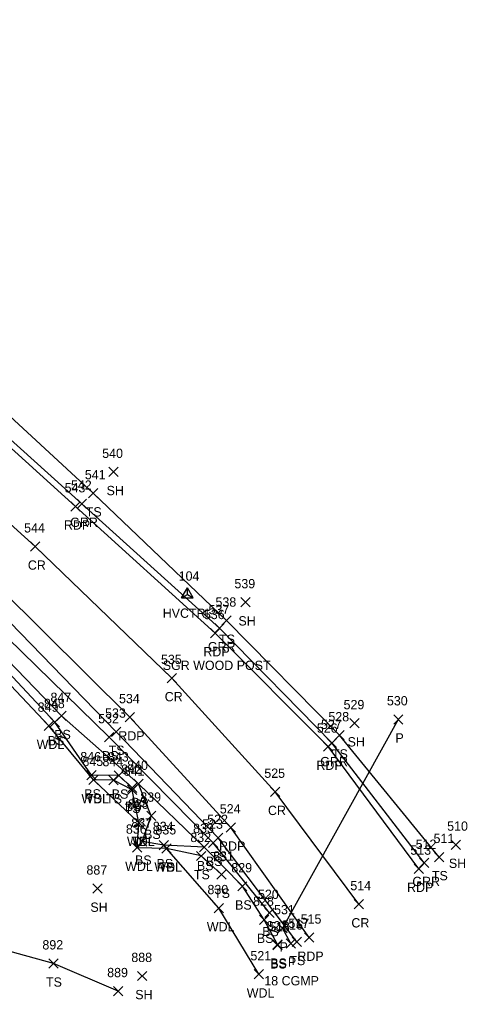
# Model space of a CAD drawing. Extents: x 1879695 to 1880991, y 836466 to 845172.
# Drawn here: x 1880183.9 to 1880280.2, y 844011.6 to 844222.2 of the extents above; entities that cross this region are included whole.
import ezdxf

# ---------------------------------------------------------------- set-up
doc = ezdxf.new("R2010")
doc.units = 0
for name, color, linetype in [('C_A', 7, 'Continuous'), ('C_I', 7, 'Continuous'), ('CPSM', 7, 'Continuous'), ('D_A', 7, 'Continuous'), ('D_C', 7, 'Continuous'), ('D_I', 7, 'Continuous'), ('D_TIC', 7, 'Continuous'), ('DCP', 7, 'Continuous'), ('L_A', 7, 'Continuous'), ('L_I', 7, 'Continuous'), ('L_TIC', 7, 'Continuous'), ('LAWA', 7, 'Continuous'), ('LELB', 7, 'Continuous'), ('P_A', 7, 'Continuous'), ('P_I', 7, 'Continuous'), ('P_TIC', 7, 'Continuous'), ('PET', 7, 'Continuous'), ('PRC', 7, 'Continuous'), ('R_A', 7, 'Continuous'), ('R_C', 7, 'Continuous'), ('R_I', 7, 'Continuous'), ('R_TIC', 7, 'Continuous'), ('RGR', 7, 'Continuous')]:
    doc.layers.add(name, color=color, linetype=linetype)

msp = doc.modelspace()

# ---------------------------------------------------------------- linework, layer by layer
at = {"layer": 'CPSM'}
for p, q in [((1880218.77, 844097.87), (1880220.02, 844100.03)), ((1880221.27, 844097.87), (1880220.02, 844100.03)), ((1880220.02, 844098.59), (1880220.02, 844100.03)), ((1880218.77, 844097.87), (1880220.02, 844098.59)), ((1880218.77, 844097.87), (1880221.27, 844097.87)), ((1880220.02, 844098.59), (1880220.02, 844098.59)), ((1880220.02, 844098.59), (1880221.27, 844097.87))]:
    msp.add_line(p, q, dxfattribs=at)
at = {"layer": 'D_TIC'}
for points in [[(1880264.37, 844070.77), (1880266.37, 844072.77)], [(1880266.37, 844070.77), (1880264.37, 844072.77)], [(1880239.44, 844025.87), (1880241.44, 844027.87)], [(1880241.44, 844025.87), (1880239.44, 844027.87)], [(1880239.44, 844025.87), (1880241.44, 844027.87)], [(1880241.44, 844025.87), (1880239.44, 844027.87)], [(1880241.26, 844022.59), (1880243.26, 844024.59)], [(1880243.26, 844022.59), (1880241.26, 844024.59)]]:
    msp.add_lwpolyline(points, dxfattribs=at)
at = {"layer": 'DCP'}
for points in [[(1880265.37, 844071.77), (1880240.44, 844026.87)], [(1880242.26, 844023.59), (1880240.44, 844026.87)]]:
    msp.add_lwpolyline(points, dxfattribs=at)
at = {"layer": 'L_TIC'}
for points in [[(1880203.15, 844123.95), (1880205.15, 844125.95)], [(1880205.15, 844123.95), (1880203.15, 844125.95)], [(1880198.77, 844119.37), (1880200.77, 844121.37)], [(1880200.77, 844119.37), (1880198.77, 844121.37)], [(1880231.5, 844095.94), (1880233.5, 844097.94)], [(1880233.5, 844095.94), (1880231.5, 844097.94)], [(1880227.42, 844091.99), (1880229.42, 844093.99)], [(1880229.42, 844091.99), (1880227.42, 844093.99)], [(1880190.54, 844070.18), (1880192.54, 844072.18)], [(1880192.54, 844070.18), (1880190.54, 844072.18)], [(1880191.94, 844071.51), (1880193.94, 844073.51)], [(1880193.94, 844071.51), (1880191.94, 844073.51)], [(1880254.97, 844069.94), (1880256.97, 844071.94)], [(1880256.97, 844069.94), (1880254.97, 844071.94)], [(1880189.2, 844069.4), (1880191.2, 844071.4)], [(1880191.2, 844069.4), (1880189.2, 844071.4)], [(1880203.68, 844068.12), (1880205.68, 844070.12)], [(1880205.68, 844068.12), (1880203.68, 844070.12)], [(1880202.19, 844066.94), (1880204.19, 844068.94)], [(1880204.19, 844066.94), (1880202.19, 844068.94)], [(1880251.69, 844067.34), (1880253.69, 844069.34)], [(1880253.69, 844067.34), (1880251.69, 844069.34)], [(1880198.4, 844058.75), (1880200.4, 844060.75)], [(1880200.4, 844058.75), (1880198.4, 844060.75)], [(1880198.81, 844057.74), (1880200.81, 844059.74)], [(1880200.81, 844057.74), (1880198.81, 844059.74)], [(1880198.81, 844057.74), (1880200.81, 844059.74)], [(1880200.81, 844057.74), (1880198.81, 844059.74)], [(1880203.13, 844057.69), (1880205.13, 844059.69)], [(1880205.13, 844057.69), (1880203.13, 844059.69)], [(1880204.3, 844058.71), (1880206.3, 844060.71)], [(1880206.3, 844058.71), (1880204.3, 844060.71)], [(1880207.11, 844055.64), (1880209.11, 844057.64)], [(1880209.11, 844055.64), (1880207.11, 844057.64)], [(1880207.14, 844056.06), (1880209.14, 844058.06)], [(1880209.14, 844056.06), (1880207.14, 844058.06)], [(1880208.51, 844056.91), (1880210.51, 844058.91)], [(1880210.51, 844056.91), (1880208.51, 844058.91)], [(1880208.51, 844056.91), (1880210.51, 844058.91)], [(1880210.51, 844056.91), (1880208.51, 844058.91)], [(1880211.26, 844050.06), (1880213.26, 844052.06)], [(1880213.26, 844050.06), (1880211.26, 844052.06)], [(1880208.6, 844048.55), (1880210.6, 844050.55)], [(1880210.6, 844048.55), (1880208.6, 844050.55)], [(1880208.6, 844048.55), (1880210.6, 844050.55)], [(1880210.6, 844048.55), (1880208.6, 844050.55)], [(1880225.64, 844045.28), (1880227.64, 844047.28)], [(1880227.64, 844045.28), (1880225.64, 844047.28)], [(1880208.22, 844043.19), (1880210.22, 844045.19)], [(1880210.22, 844043.19), (1880208.22, 844045.19)], [(1880209.32, 844044.52), (1880211.32, 844046.52)], [(1880211.32, 844044.52), (1880209.32, 844046.52)], [(1880213.95, 844043.76), (1880215.95, 844045.76)], [(1880215.95, 844043.76), (1880213.95, 844045.76)], [(1880214.51, 844043.03), (1880216.51, 844045.03)], [(1880216.51, 844043.03), (1880214.51, 844045.03)], [(1880214.51, 844043.03), (1880216.51, 844045.03)], [(1880216.51, 844043.03), (1880214.51, 844045.03)], [(1880222.61, 844043.33), (1880224.61, 844045.33)], [(1880224.61, 844043.33), (1880222.61, 844045.33)], [(1880222.61, 844043.33), (1880224.61, 844045.33)], [(1880224.61, 844043.33), (1880222.61, 844045.33)], [(1880224.55, 844044.25), (1880226.55, 844046.25)], [(1880226.55, 844044.25), (1880224.55, 844046.25)], [(1880276.75, 844043.83), (1880278.75, 844045.83)], [(1880278.75, 844043.83), (1880276.75, 844045.83)], [(1880222.01, 844041.4), (1880224.01, 844043.4)], [(1880224.01, 844041.4), (1880222.01, 844043.4)], [(1880273.18, 844041.18), (1880275.18, 844043.18)], [(1880275.18, 844041.18), (1880273.18, 844043.18)], [(1880226.34, 844037.4), (1880228.34, 844039.4)], [(1880228.34, 844037.4), (1880226.34, 844039.4)], [(1880199.67, 844034.4), (1880201.67, 844036.4)], [(1880201.67, 844034.4), (1880199.67, 844036.4)], [(1880230.83, 844034.88), (1880232.83, 844036.88)], [(1880232.83, 844034.88), (1880230.83, 844036.88)], [(1880225.78, 844030.19), (1880227.78, 844032.19)], [(1880227.78, 844030.19), (1880225.78, 844032.19)], [(1880236.65, 844029.17), (1880238.65, 844031.17)], [(1880238.65, 844029.17), (1880236.65, 844031.17)], [(1880235.51, 844027.71), (1880237.51, 844029.71)], [(1880237.51, 844027.71), (1880235.51, 844029.71)], [(1880238.37, 844022.21), (1880240.37, 844024.21)], [(1880240.37, 844022.21), (1880238.37, 844024.21)], [(1880238.41, 844022.39), (1880240.41, 844024.39)], [(1880240.41, 844022.39), (1880238.41, 844024.39)], [(1880238.41, 844022.39), (1880240.41, 844024.39)], [(1880240.41, 844022.39), (1880238.41, 844024.39)], [(1880242.53, 844022.94), (1880244.53, 844024.94)], [(1880244.53, 844022.94), (1880242.53, 844024.94)], [(1880190.21, 844018.31), (1880192.21, 844020.31)], [(1880192.21, 844018.31), (1880190.21, 844020.31)], [(1880209.32, 844015.61), (1880211.32, 844017.61)], [(1880211.32, 844015.61), (1880209.32, 844017.61)], [(1880234.36, 844015.97), (1880236.36, 844017.97)], [(1880236.36, 844015.97), (1880234.36, 844017.97)], [(1880204.14, 844012.35), (1880206.14, 844014.35)], [(1880206.14, 844012.35), (1880204.14, 844014.35)]]:
    msp.add_lwpolyline(points, dxfattribs=at)
at = {"layer": 'LAWA'}
msp.add_lwpolyline([(1880235.36, 844016.97), (1880226.78, 844031.19), (1880215.51, 844044.03), (1880209.22, 844044.19), (1880209.6, 844049.55), (1880199.81, 844058.74), (1880190.2, 844070.4), (1880171.48, 844090.23), (1880169.04, 844093.32), (1880159.9, 844092.48), (1880155.76, 844084.92), (1880148.42, 844091.37), (1880152.26, 844105.95), (1880144.4, 844115.49), (1880125.95, 844132.35), (1880103.11, 844152.62), (1880080.73, 844170.23), (1880061.24, 844186.41), (1880031.89, 844196.39), (1880020.4, 844184.31), (1880005.38, 844176.44), (1879986.51, 844163.82)], dxfattribs=at)
at = {"layer": 'LELB'}
for points in [[(1880237.65, 844030.17), (1880225.55, 844045.25), (1880203.19, 844067.94), (1880175.04, 844095.38), (1880141.55, 844124.24), (1880111.59, 844152.12), (1880079.67, 844179.09), (1880044.89, 844208.16), (1880013.5, 844237.54), (1880003.34, 844247.82), (1879979.16, 844270.62), (1879948.51, 844300.87), (1879928.97, 844335.67), (1879901.59, 844373.87), (1879881.39, 844405.75), (1879863.37, 844445.07), (1879846.41, 844479.41), (1879833.35, 844517.23), (1879821, 844560.9), (1879811.24, 844600.26), (1879800.64, 844646.71), (1879794.2, 844680.16), (1879792.03, 844683.6), (1879789.08, 844683.63)], [(1880243.53, 844023.94), (1880226.64, 844046.28), (1880204.68, 844069.12), (1880177.19, 844097.39), (1880144.15, 844127.37), (1880114.34, 844154.46), (1880082.65, 844181.38), (1880047.53, 844211.78), (1880015.32, 844240.12), (1879982.29, 844271.84), (1879951.96, 844303.04), (1879930.28, 844336.91), (1879904.08, 844374.32), (1879883.92, 844406.9), (1879866.98, 844446.02), (1879852.23, 844482.49), (1879838.68, 844519.35), (1879826.86, 844562.48), (1879815.22, 844600.52)], [(1880274.18, 844042.18), (1880252.69, 844068.34), (1880228.42, 844092.99), (1880199.77, 844120.37), (1880165.71, 844151.73), (1880135.43, 844177.69), (1880104.5, 844206.3), (1880070.17, 844236.88), (1880037.83, 844267.79), (1880007.31, 844296.06), (1879981.71, 844326.11), (1879957.94, 844357.83), (1879934.98, 844394.4), (1879917.02, 844424.23)], [(1880208.14, 844057.06), (1880205.3, 844059.71), (1880199.4, 844059.75), (1880191.54, 844071.18), (1880172.4, 844091.6), (1880168.93, 844094.5), (1880159.81, 844093.84), (1880155.76, 844086.44), (1880150.38, 844091.63), (1880154.09, 844106.65), (1880145.11, 844116.32), (1880126.55, 844133.72), (1880103.74, 844153.59), (1880081.3, 844171.15), (1880062.9, 844187.7), (1880046.08, 844200.5), (1880030.27, 844215.53), (1880015.96, 844231.11), (1880002.51, 844242.73), (1879985.64, 844257.52)], [(1880223.61, 844044.33), (1880209.51, 844057.91), (1880192.94, 844072.51), (1880173.59, 844092.48), (1880156.34, 844108.5), (1880145.52, 844117.21), (1880140.19, 844123.17), (1880127.57, 844134.43), (1880104.95, 844154.51), (1880082.15, 844172.53), (1880063.54, 844188.27), (1880047.18, 844201.5), (1880031.58, 844216.92), (1880015.96, 844231.11)], [(1880205.14, 844013.35), (1880191.21, 844019.31), (1880170.65, 844024.97), (1880149.68, 844023.18), (1880131.81, 844038.78), (1880122.52, 844049.64), (1880090.54, 844059.6), (1880064.96, 844073.97), (1880039.21, 844084.61)], [(1880209.6, 844049.55), (1880208.11, 844056.64), (1880204.13, 844058.69), (1880199.81, 844058.74)], [(1880239.41, 844023.39), (1880236.51, 844028.71), (1880231.83, 844035.88), (1880223.61, 844044.33), (1880214.95, 844044.76), (1880210.32, 844045.52), (1880212.26, 844051.06), (1880209.51, 844057.91)], [(1880227.34, 844038.4), (1880223.01, 844042.4), (1880215.51, 844044.03)], [(1880239.37, 844023.21), (1880239.41, 844023.39)]]:
    msp.add_lwpolyline(points, dxfattribs=at)
at = {"layer": 'P_TIC'}
for points in [[(1880194.98, 844116.55), (1880196.98, 844118.55)], [(1880196.98, 844116.55), (1880194.98, 844118.55)], [(1880186.27, 844107.93), (1880188.27, 844109.93)], [(1880188.27, 844107.93), (1880186.27, 844109.93)], [(1880224.97, 844089.31), (1880226.97, 844091.31)], [(1880226.97, 844089.31), (1880224.97, 844091.31)], [(1880215.7, 844079.65), (1880217.7, 844081.65)], [(1880217.7, 844079.65), (1880215.7, 844081.65)], [(1880206.67, 844071.23), (1880208.67, 844073.23)], [(1880208.67, 844071.23), (1880206.67, 844073.23)], [(1880249.27, 844064.9), (1880251.27, 844066.9)], [(1880251.27, 844064.9), (1880249.27, 844066.9)], [(1880237.91, 844055.2), (1880239.91, 844057.2)], [(1880239.91, 844055.2), (1880237.91, 844057.2)], [(1880228.35, 844047.54), (1880230.35, 844049.54)], [(1880230.35, 844047.54), (1880228.35, 844049.54)], [(1880268.75, 844038.67), (1880270.75, 844040.67)], [(1880270.75, 844038.67), (1880268.75, 844040.67)], [(1880255.85, 844031.04), (1880257.85, 844033.04)], [(1880257.85, 844031.04), (1880255.85, 844033.04)], [(1880245.17, 844023.86), (1880247.17, 844025.86)], [(1880247.17, 844023.86), (1880245.17, 844025.86)]]:
    msp.add_lwpolyline(points, dxfattribs=at)
at = {"layer": 'PET'}
for points in [[(1880269.75, 844039.67), (1880250.27, 844065.9), (1880225.97, 844090.31), (1880195.98, 844117.55), (1880162.1, 844148.13), (1880132.62, 844174.7), (1880101.36, 844203.03), (1880066.94, 844232.59), (1880034.5, 844263.16), (1880004.09, 844293.64), (1879978.17, 844323.39), (1879954.46, 844354.82), (1879930.76, 844391.37), (1879912.37, 844423.12), (1879894.17, 844458.9), (1879879.41, 844492.34), (1879865.46, 844529.81), (1879852.88, 844569.32), (1879843.17, 844608.03)], [(1880246.17, 844024.86), (1880229.35, 844048.54), (1880207.67, 844072.23), (1880179.65, 844099.99), (1880146.48, 844130.19), (1880116.3, 844156.76), (1880085.61, 844184.86), (1880050.42, 844215.32), (1880017.65, 844245.83), (1879986.99, 844277.13), (1879959.04, 844308.59), (1879934.2, 844340.79), (1879910.26, 844378.73), (1879891.14, 844411.43), (1879872.36, 844448.44), (1879856.33, 844484.43), (1879842.37, 844521.56), (1879829.6, 844563.28), (1879820.43, 844602.23)]]:
    msp.add_lwpolyline(points, dxfattribs=at)
at = {"layer": 'PRC'}
msp.add_lwpolyline([(1880256.85, 844032.04), (1880238.91, 844056.2), (1880216.7, 844080.65), (1880187.27, 844108.93), (1880154.23, 844138.82), (1880124.19, 844165.48), (1880092.74, 844193.41), (1880058.56, 844223.39), (1880025.99, 844253.92), (1879995.14, 844285.41), (1879968.79, 844316.24), (1879945.09, 844347.91), (1879920.67, 844385.19), (1879902.45, 844417.14), (1879883.72, 844454.21), (1879868.53, 844488.38), (1879854.47, 844526.01), (1879841.81, 844566.38), (1879832.13, 844605)], dxfattribs=at)
at = {"layer": 'R_TIC'}
for points in [[(1880196.34, 844117.12), (1880198.34, 844119.12)], [(1880198.34, 844117.12), (1880196.34, 844119.12)], [(1880225.93, 844090.38), (1880227.93, 844092.38)], [(1880227.93, 844090.38), (1880225.93, 844092.38)], [(1880250.09, 844065.69), (1880252.09, 844067.69)], [(1880252.09, 844065.69), (1880250.09, 844067.69)], [(1880269.9, 844039.93), (1880271.9, 844041.93)], [(1880271.9, 844039.93), (1880269.9, 844041.93)]]:
    msp.add_lwpolyline(points, dxfattribs=at)
at = {"layer": 'RGR'}
msp.add_lwpolyline([(1880270.9, 844040.93), (1880251.09, 844066.69), (1880226.93, 844091.38), (1880197.34, 844118.12), (1880162.87, 844149.15), (1880133.45, 844175.62), (1880101.92, 844203.72), (1880067.67, 844234.21), (1880035.3, 844264.37), (1880005.3, 844294.8), (1879979.45, 844324.37), (1879956.29, 844356.24), (1879932.57, 844392.56), (1879914.54, 844423.96), (1879896.38, 844459.86), (1879881.66, 844493.03), (1879867.6, 844530.61), (1879855.21, 844570.01), (1879845.36, 844608.98)], dxfattribs=at)

# ---------------------------------------------------------------- texts
at = {"layer": 'C_A'}
msp.add_text('HVCTRL', height=2, dxfattribs=at).set_placement((1880214.71, 844093.59))
at = {"layer": 'C_I'}
msp.add_text('104', height=2, dxfattribs=at).set_placement((1880218.14, 844101.59))
at = {"layer": 'D_A'}
for p in [(1880264.75, 844066.77), (1880239.82, 844021.87), (1880239.82, 844021.87), (1880241.63, 844018.59)]:
    msp.add_text('P', height=2, dxfattribs=at).set_placement(p)
at = {"layer": 'D_C'}
msp.add_text('18 CGMP', height=2, dxfattribs=at).set_placement((1880236.55, 844014.59))
at = {"layer": 'D_I'}
for s, p in [('530', (1880262.92, 844074.77)), ('531', (1880238.65, 844029.87)), ('531', (1880238.65, 844029.87)), ('516', (1880240.4, 844026.59))]:
    msp.add_text(s, height=2, dxfattribs=at).set_placement(p)
at = {"layer": 'L_A'}
for s, p in [('SH', (1880202.64, 844119.95)), ('TS', (1880198.17, 844115.37)), ('SH', (1880230.99, 844091.94)), ('TS', (1880226.83, 844087.99)), ('BS', (1880189.98, 844066.18)), ('BS', (1880191.38, 844067.51)), ('SH', (1880254.46, 844065.94)), ('WDL', (1880187.62, 844065.4)), ('TS', (1880203.09, 844064.12)), ('BS', (1880201.64, 844062.94)), ('TS', (1880251.1, 844063.34)), ('WDL', (1880197.23, 844053.74)), ('BS', (1880197.84, 844054.75)), ('TS', (1880198.22, 844053.74)), ('TS', (1880202.54, 844053.69)), ('BS', (1880203.75, 844054.71)), ('TS', (1880206.52, 844051.64)), ('BS', (1880206.58, 844052.06)), ('BS', (1880207.96, 844052.91)), ('BS', (1880207.96, 844052.91)), ('BS', (1880210.7, 844046.06)), ('WDL', (1880207.02, 844044.55)), ('TS', (1880208.01, 844044.55)), ('BS', (1880208.76, 844040.52)), ('TS', (1880225.05, 844041.28)), ('WDL', (1880206.63, 844039.19)), ('WDL', (1880212.92, 844039.03)), ('BS', (1880213.39, 844039.76)), ('TS', (1880213.91, 844039.03)), ('BS', (1880222.05, 844039.33)), ('BS', (1880222.05, 844039.33)), ('BS', (1880223.99, 844040.25)), ('SH', (1880276.24, 844039.83)), ('TS', (1880221.42, 844037.4)), ('TS', (1880272.59, 844037.18)), ('TS', (1880225.75, 844033.4)), ('SH', (1880199.16, 844030.4)), ('BS', (1880230.27, 844030.88)), ('WDL', (1880224.2, 844026.19)), ('BS', (1880234.95, 844023.71)), ('BS', (1880236.09, 844025.17)), ('BS', (1880237.81, 844018.21)), ('BS', (1880237.85, 844018.39)), ('BS', (1880237.85, 844018.39)), ('TS', (1880241.94, 844018.94)), ('TS', (1880189.62, 844014.31)), ('SH', (1880208.81, 844011.61)), ('WDL', (1880232.78, 844011.97))]:
    msp.add_text(s, height=2, dxfattribs=at).set_placement(p)
at = {"layer": 'L_I'}
for s, p in [('540', (1880201.7, 844127.95)), ('541', (1880197.97, 844123.37)), ('539', (1880230.13, 844099.94)), ('538', (1880226.06, 844095.99)), ('848', (1880189.18, 844074.18)), ('847', (1880190.58, 844075.51)), ('849', (1880187.83, 844073.4)), ('533', (1880202.32, 844072.12)), ('529', (1880253.6, 844073.94)), ('532', (1880200.83, 844070.94)), ('528', (1880250.33, 844071.34)), ('846', (1880196.99, 844062.75)), ('845', (1880197.45, 844061.74)), ('845', (1880197.45, 844061.74)), ('844', (1880201.76, 844061.69)), ('843', (1880202.94, 844062.71)), ('842', (1880205.78, 844060.06)), ('841', (1880206.32, 844059.64)), ('840', (1880207.07, 844060.91)), ('840', (1880207.07, 844060.91)), ('839', (1880209.89, 844054.06)), ('838', (1880207.24, 844052.55)), ('838', (1880207.24, 844052.55)), ('522', (1880224.28, 844049.28)), ('836', (1880206.8, 844047.19)), ('837', (1880207.96, 844048.52)), ('834', (1880212.59, 844047.76)), ('835', (1880213.14, 844047.03)), ('835', (1880213.14, 844047.03)), ('833', (1880221.24, 844047.33)), ('833', (1880221.24, 844047.33)), ('523', (1880223.19, 844048.25)), ('510', (1880275.87, 844047.83)), ('832', (1880220.65, 844045.4)), ('511', (1880272.95, 844045.18)), ('831', (1880225.55, 844041.4)), ('887', (1880198.31, 844038.4)), ('829', (1880229.46, 844038.88)), ('830', (1880224.33, 844034.19)), ('520', (1880235.2, 844033.17)), ('828', (1880234.14, 844031.71)), ('827', (1880237.05, 844026.39)), ('827', (1880237.05, 844026.39)), ('518', (1880237.57, 844026.21)), ('517', (1880241.73, 844026.94)), ('892', (1880188.84, 844022.31)), ('888', (1880207.96, 844019.61)), ('521', (1880233.57, 844019.97)), ('889', (1880202.77, 844016.35))]:
    msp.add_text(s, height=2, dxfattribs=at).set_placement(p)
at = {"layer": 'P_A'}
for s, p in [('RDP', (1880193.47, 844112.55)), ('CR', (1880185.71, 844103.93)), ('RDP', (1880223.46, 844085.31)), ('CR', (1880215.14, 844075.65)), ('RDP', (1880205.16, 844067.23)), ('RDP', (1880247.76, 844060.9)), ('CR', (1880237.34, 844051.2)), ('RDP', (1880226.83, 844043.54)), ('RDP', (1880267.24, 844034.67)), ('CR', (1880255.28, 844027.04)), ('RDP', (1880243.66, 844019.86))]:
    msp.add_text(s, height=2, dxfattribs=at).set_placement(p)
at = {"layer": 'P_I'}
for s, p in [('543', (1880193.62, 844120.55)), ('544', (1880184.91, 844111.93)), ('536', (1880223.56, 844093.31)), ('535', (1880214.34, 844083.65)), ('534', (1880205.31, 844075.23)), ('526', (1880247.85, 844068.9)), ('525', (1880236.55, 844059.2)), ('524', (1880226.98, 844051.54)), ('513', (1880267.95, 844042.67)), ('514', (1880255.05, 844035.04)), ('515', (1880244.37, 844027.86))]:
    msp.add_text(s, height=2, dxfattribs=at).set_placement(p)
at = {"layer": 'R_A'}
for p in [(1880194.83, 844113.12), (1880224.42, 844086.38), (1880248.58, 844061.69), (1880268.39, 844035.93)]:
    msp.add_text('GRR', height=2, dxfattribs=at).set_placement(p)
at = {"layer": 'R_C'}
msp.add_text('SGR WOOD POST', height=2, dxfattribs=at).set_placement((1880214.72, 844082.38))
at = {"layer": 'R_I'}
for s, p in [('542', (1880194.98, 844121.12)), ('537', (1880224.57, 844094.38)), ('527', (1880248.73, 844069.69)), ('512', (1880269.1, 844043.93))]:
    msp.add_text(s, height=2, dxfattribs=at).set_placement(p)

doc.saveas('drawing.dxf')
